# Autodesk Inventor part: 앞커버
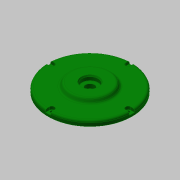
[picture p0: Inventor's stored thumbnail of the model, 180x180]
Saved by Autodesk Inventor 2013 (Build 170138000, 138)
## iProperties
Created: 2016-11
Part Number: 앞커버
Material: 일반
Document SubType Name: Modeling
Designer: mduedu
Density: 2.71 g/cm^3
Mass: 511.35 g
Surface Area: 365.029 cm^2
Volume: 188.69 cm^3
Author: mduedu
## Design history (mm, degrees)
sketch "스케치1"
  geometry: L1 (22, -12.5)-(22, -30); L2 (22, -30)-(16, -33.464); L3 (16, -33.464)-(16, -65); L4 (16, -65)-(8, -65); L5 (8, -65)-(8, -53); L6 (8, -53)-(0, -53); L7 (0, -53)-(0, -14); L8 (0, 0)-(22, 0); L9 (8, -14)-(8, -7); L10 (8, -7)-(14.5, -7); L11 (14.5, -7)-(14.5, -12.5); L12 (0, -14)-(8, -14); L13 (14.5, -12.5)-(22, -12.5)
  constraints: 26 end point, 8 parallel, 3 perpendicular, 2 horizontal, 2 vertical alignment, 1 collinear
  dimensions: "d0" = 8 distance of L5.end L6.end; "d2" = 8 distance of L3.end L4.end; "d3" = 6 distance between parallel lines of L1 L3; "d4" = 120 deg angle of L3 L2; "d5" = 7.5 distance of L11.end L1.start; "d6" = 60 diameter of L1.end L8; "d7" = 14 diameter of L10 L8; "d8" = 28 diameter of L12 L8; "d9" = 25 diameter of L13 L8; "d10" = 106 diameter of L6 L8; "d11" = 130 diameter of L4 L8
revolve "회전1" sketch "스케치1" stored, may be unused: angle "d12" = 90 deg
fillet "모깎기1" dims "d13" = 0.3
fillet "모깎기2" dims "d14" = 3
chamfer "모따기1" distance "d15" = 1; stored, may be unused: second distance "d16" = 2, angle "d17" = 45 deg
fillet "모깎기3" dims "d18" = 0.3
chamfer "모따기2" distance "d36" = 2; stored, may be unused: second distance "d37" = 2, angle "d38" = 30 deg
sketch "스케치3"
  geometry: C1 r 65 at (0, 0) reference; A1 r 59 centre (0, 0) between (0, 59) and (59, 0); 2 further points
  constraints: 4 point on circle, 2 horizontal alignment, 2 vertical alignment, 1 centre point, 1 coincident
  dimensions: "d33" = 118 diameter of A1
sketch "스케치4"
  geometry: 4 further points
  constraints: 4 other
hole "구멍2" sketch "스케치4" at (0, 59), (-59, 0), (59, 0), (0, -59) diameter "d39" = 4.5; stored, may be unused: countersink angle "d43" = 90 deg, drill point angle "d45" = 0 deg; dims "d40" = 6, "d41" = 8, "d42" = 4.6, "d44" = 8
sketch "스케치6"
  geometry: L1 (-4, 5.877)-(-4, 0); L2 (4, 5.877)-(4, 0); A1 r 4 centre (0, 0) between (-2.712, 2.941) and (2.712, 2.941) reference; A2 r 65 centre (0, -59) between (-4, 5.877) and (4, 5.877) reference; 1 further point
  constraints: 4 end point, 4 point on circle, 2 tangent, 2 vertical
extrude "돌출2" cut sketch "스케치6" stored distance "d51" = 10; taper "d52" = 0 deg
sketch "스케치5"
  geometry: C1 r 22 at (0, 0); C2 r 45 at (0, 0); 1 further point
  constraints: 2 centre point, 2 coincident
  dimensions: "d46" = 44 diameter of C1; "d47" = 90 diameter of C2
extrude "돌출1" cut sketch "스케치5" distance "d48" = 8; taper "d49" = 0 deg
fillet "모깎기4" dims "d50" = 3
node "솔리드1"
pattern_circular "원형 패턴1" dims angle "d54" = 360 deg
